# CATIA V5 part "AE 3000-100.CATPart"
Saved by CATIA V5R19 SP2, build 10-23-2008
Part number: AE 3000-100
Bounding box of the stored display mesh (mm): x -47.487 to 47.487, y -47.487 to 47.487, z 0 to 270
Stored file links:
  C:\Users\Bora\Desktop\3D Katı model\AE serisi\AE 3000\AE 3000-100.CATPart
  C:\Program Files\Dassault Systemes\B19\intel_a\reffiles\standard\MetricThickPitch.txt
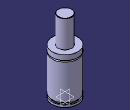
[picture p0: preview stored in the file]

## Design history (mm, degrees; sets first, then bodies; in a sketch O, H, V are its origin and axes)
Body1 (main body)
  Sketch1 on yz-plane, origin (0, 0, 0), H (0, 1, 0), V (0, 0, 1)
    point P1 (47.5, 150.5)
    point P5 (25, 269)
    point P7 (25, 269)
    point P12 (47.5, 145.5)
    point P13 (47.5, 150.5)
    point P14 (47.5, 145.5)
    line L1 (47.5, 150.5) -> (47.5, 169)
    line L2 (47.5, 0) -> (47.5, 8)
    arc A1 centre (24, 269) radius 1 from (25, 269) to (24, 270) ccw
    line L3 (25, 269) -> (25, 169)
    line L4 (43.5, 15) -> (43.5, 8)
    line L5 (47.5, 15) -> (47.5, 145.5)
    arc A2 centre (47.5, 148) radius 2.5 from (47.5, 150.5) to (47.5, 145.5) ccw
    line L6 (24, 270) -> (0, 270)
    point P15 (0, 270)
    line L7 (25, 169) -> (47.5, 169)
    line L8 (0, 0) -> (47.5, 0)
    line L9 (43.5, 15) -> (47.5, 15)
    line L10 (43.5, 8) -> (47.5, 8)
    coincidence: P15 V, P1 P13, P5 P7, P12 P14
    tangency: L6 A1
    horizontal: L7 H, L8 H, L9 H, L10 H
  Shaft1: profile Sketch1, axis Sketch1.V, angle 360
  Sketch2 on face of Shaft1 from Sketch1.L8, origin (0, 0, 0), H (1, 0, 0), V (0, -1, 0)
    point P1 (30, 0)
    distance P1 V = 30
  Hole1: placed by Sketch2, at (30, 0, 0) direction (0, 0, 1), diameter 6.647, depth 13, threaded "M8", thread diameter 8, thread depth 13, pitch 1.25
  CircPattern1: of Hole1, instances 4, angular step 90, axis from xy-plane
